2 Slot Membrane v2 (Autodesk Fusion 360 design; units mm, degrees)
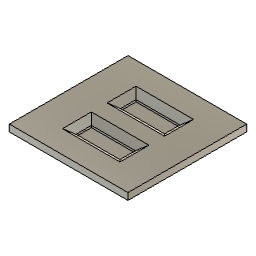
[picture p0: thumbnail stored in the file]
sketch "Sketch1" plane through (0, 0, 0) normal (0, 0, 1) x axis (1, 0, 0)
  line L1 (5.4, 0) -> (0, 0)
  line L2 (5.4, 5.4) -> (5.4, 0)
  line L3 (0, 5.4) -> (5.4, 5.4)
  line L4 (0, 0) -> (0, 5.4)
  point P1 (0, 0)
  point P2 (0, 0)
  point P5 (0, 5.4)
  horizontal L1
  vertical L2
  horizontal L3
  vertical L4
  coincident P1 P2
  dimension "d1" distance P2 P5 = 5.4
  dimension "d2" distance L2 L4 = 5.4
extrude "Extrude1" new body sketch "Sketch1" along normal blind 0.31
sketch "Sketch2" plane through (0, 0, 0.31) normal (0, 0, 1) x axis (-1, 0, 0)
  line L1 (-3.7, -4.065) -> (-1.7, -4.065)
  line L2 (-3.7, -3.365) -> (-3.7, -4.065)
  line L3 (-1.7, -3.365) -> (-3.7, -3.365)
  line L4 (-1.7, -4.065) -> (-1.7, -3.365)
  line L5 (-3.7, -2.035) -> (-1.7, -2.035)
  line L6 (-3.7, -1.335) -> (-3.7, -2.035)
  line L7 (-1.7, -1.335) -> (-3.7, -1.335)
  line L8 (-1.7, -2.035) -> (-1.7, -1.335)
  line L9 (-5.4, 0) -> (0, 0)
  line L10 (-5.4, -5.4) -> (-5.4, 0)
  line L11 (0, -5.4) -> (-5.4, -5.4)
  line L12 (0, 0) -> (0, -5.4)
  line L13 (-5.4, -2.7) -> (0, -2.7)
  line L14 (-2.7, -2.035) -> (-2.7, -3.365)
  line L15 (0, 0) -> (0, -5.4)
  line L16 (-5.4, 0) -> (0, 0)
  line L17 (-5.4, -5.4) -> (-5.4, 0)
  line L18 (0, -5.4) -> (-5.4, -5.4)
  point P1 (0, 0)
  point P10 (0, 0)
  point P14 (0, -2.7)
  point P15 (-5.4, -2.7)
  point P16 (-2.7, -3.365)
  point P17 (-2.7, -2.035)
  horizontal L1
  vertical L2
  horizontal L3
  vertical L4
  horizontal L5
  vertical L6
  horizontal L7
  vertical L8
  horizontal L9
  vertical L10
  horizontal L11
  vertical L12
  coincident P1 P10
  coincident L12 P14
  coincident L10 P15
  perpendicular L10 L13
  midpoint L12 P14
  midpoint L3 P16
  midpoint L5 P17
  midpoint L13 L14
  dimension "d8" distance L6 L8 = 2
  dimension "d9" distance L5 L7 = 0.7
  dimension "d10" distance L2 L4 = 2
  dimension "d11" distance L1 L3 = 0.7
  dimension "d12" distance L3 L5 = 1.33
  dimension "d13" distance L10 L12 = 5.4
  dimension "d14" distance L9 L11 = 5.4
  dimension "d15" distance L2 L10 = 1.7
extrude "Extrude2" cut sketch "Sketch2" profile of L1 L2 L3 L4 L5 L6 L7 L8 against normal blind 2
chamfer "Chamfer2" distance 0.31 Rotate Angle 35.3
sketch "Sketch3" plane through (0, 0, 0) normal (0, 0, -1) x axis (1, 0, 0)
  line L1 (3.7, -2.035) -> (3.7, -1.335)
  line L2 (1.7, -2.035) -> (3.7, -2.035)
  line L3 (1.7, -1.335) -> (1.7, -2.035)
  line L4 (3.7, -1.335) -> (1.7, -1.335)
  line L5 (3.7, -4.065) -> (3.7, -3.365)
  line L6 (1.7, -4.065) -> (3.7, -4.065)
  line L7 (1.7, -3.365) -> (1.7, -4.065)
  line L8 (3.7, -3.365) -> (1.7, -3.365)
  line L9 (0, -5.4) -> (0, 0)
  line L10 (5.4, -5.4) -> (0, -5.4)
  line L11 (5.4, 0) -> (5.4, -5.4)
  line L12 (0, 0) -> (5.4, 0)
place_component sketch "Sketch3"
extrude "Extrude1" new body sketch "Sketch3" along normal blind 0.0001 (= "100 nm")
component_from_bodies "Body->Comp"
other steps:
base_feature "Base Feature"
create_component "CreateComponent1" sketch "Sketch3"
create_component "CreateComponent2"
remove_body "RemoveBody1"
